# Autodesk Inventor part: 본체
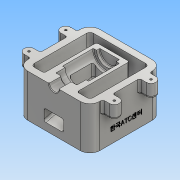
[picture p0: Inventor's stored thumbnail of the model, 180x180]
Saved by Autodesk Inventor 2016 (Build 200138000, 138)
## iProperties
Created: 2018-01
Part Number: 본체
Material: 알루미늄 6061
Document SubType Name: Modeling
Designer: Administrator
Density: 2.7 g/cm^3
Appearance: 알루미늄 - 평지
Mass: 993.349 g
Surface Area: 839.189 cm^2
Volume: 367.907 cm^3
Author: Administrator
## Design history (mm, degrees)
sketch "스케치1"
  geometry: L1 (-55, -55)-(55, -55); L2 (55, -55)-(55, 55); L3 (55, 55)-(-55, 55); L4 (-55, 55)-(-55, -55); L5 (-55, -55)-(55, 55); L6 (55, -55)-(-55, 55); 1 further point
  constraints: 12 end point, 2 midpoint, 2 parallel, 1 horizontal, 1 perpendicular
  dimensions: "d0" = 110 distance of L3.end L2.end; "d1" = 110 distance of L2.end L1.end
extrude "돌출1" new body sketch "스케치1" distance "d2" = 65; taper "d3" = 0 deg
sketch "스케치2"
  geometry: L1 (-55, -55)-(55, -55) reference; L2 (55, -55)-(55, 55) reference; L3 (55, 55)-(-55, 55) reference; L4 (-55, 55)-(-55, -55) reference; L5 (-45, 45)-(45, 45); L6 (45, 45)-(45, -45); L7 (45, -45)-(-45, -45); L8 (-45, -45)-(-45, 45); 1 further point
  constraints: 8 end point, 3 other
  dimensions: "d4" = 10 distance between parallel lines of L3 L5
extrude "돌출2" cut sketch "스케치2" stored distance "d5" = 65; taper "d6" = 0 deg
sketch "스케치3"
  geometry: L1 (55, -55)-(55, 55) reference; L2 (55, 55)-(-55, 55) reference; L3 (0, 0)-(0, 91.556); L4 (0, 0)-(113.572, 0); L5 (55, 35.5)-(65, 35.5); L6 (65, 35.5)-(65, 20.5); L7 (65, 20.5)-(55, 20.5); L8 (55, 20.5)-(55, 35.5); L9 (55, -20.5)-(55, -35.5); L10 (65, -35.5)-(65, -20.5); L11 (65, -20.5)-(55, -20.5); L12 (55, -35.5)-(65, -35.5); L13 (-65, -20.5)-(-55, -20.5); L14 (-55, 35.5)-(-65, 35.5); L15 (-65, 20.5)-(-55, 20.5); L16 (-55, 20.5)-(-55, 35.5); L17 (-65, 35.5)-(-65, 20.5); L18 (-55, -35.5)-(-65, -35.5); L19 (-65, -35.5)-(-65, -20.5); L20 (-55, -20.5)-(-55, -35.5); A1 r 7.5 centre (65, 28) between (65, 20.5) and (65, 35.5); A2 r 7.5 centre (65, -28) between (65, -35.5) and (65, -20.5); A3 r 7.5 centre (-65, 28) between (-65, 35.5) and (-65, 20.5); A4 r 7.5 centre (-65, -28) between (-65, -20.5) and (-65, -35.5)
  constraints: 36 end point, 15 symmetric about line, 8 point on circle, 4 centre point, 2 horizontal, 2 parallel, 1 midpoint, 1 perpendicular, 1 point on line, 1 vertical, 3 other
  dimensions: "d7" = 10 distance between parallel lines of L6 L1; "d8" = 27 distance from line of L2 A1.centre; "d9" = 7.5 radius of A1
extrude "돌출3" join sketch "스케치3" distance "d10" = 20; taper "d11" = 0 deg
sketch "스케치4"
  geometry: L1 (-45, 65)-(-45, 0) reference; L2 (-45, 8.564)-(35, 30); L3 (35, 30)-(35, 65); L4 (45, 0)-(-45, 0) reference; L5 (55, 0)-(55, 65) reference; L6 (-45, 65)-(45, 65) reference; 1 further point
  constraints: 4 end point, 2 point on line, 1 parallel
  dimensions: "d12" = 105 deg angle of L2 L1; "d13" = 30 distance from line of L4 L2.end; "d14" = 20 distance between parallel lines of L5 L3
extrude "돌출4" join sketch "스케치4" stored distance "d15" = 50; taper "d16" = 0 deg
sketch "스케치5"
  geometry: L1 (-55, -55)-(55, -55) reference; L2 (55, 55)-(-55, 55) reference; L3 (0, 0)-(0, 68.089); L4 (0, -45)-(0, 30); L5 (-15, 30)-(-15, 25); L6 (-15, 25)-(-20, 25); L7 (-20, 25)-(-20, -22); L8 (-20, -22)-(-16, -22); L9 (-16, -22)-(-16, -36); L10 (-16, -36)-(-7.5, -36); L11 (-7.5, -36)-(-7.5, -45); L12 (-45, -45)-(45, -45) reference; L13 (-15, 30)-(0, 30); L14 (-7.5, -45)-(-7.5, -55); L15 (0, -55)-(0, -45); L16 (0, -55)-(-7.5, -55)
  constraints: 26 end point, 8 perpendicular, 3 point on line, 2 midpoint, 1 collinear, 1 parallel, 1 vertical
  dimensions: "d17" = 15 diameter of L11 L3; "d18" = 32 diameter of L9 L3; "d19" = 40 diameter of L7 L3; "d20" = 30 diameter of L5 L3; "d21" = 19 distance between parallel lines of L1 L10; "d22" = 14 distance between parallel lines of L8 L10; "d23" = 47 distance between parallel lines of L6 L8; "d24" = 5 distance between parallel lines of L6 L13
revolve "회전1" sketch "스케치5" stored, may be unused: angle "d25" = 90 deg
sketch "스케치7"
  geometry: L1 (35, 30)-(-45, 8.564) reference; L2 (20, 31.157)-(-55, 11.061); L3 (-17, 39.243)-(-55, 29.061); L4 (-55, 0)-(-55, 65) reference; L5 (20, 31.157)-(20, 45); L6 (25, 45)-(-22, 45) reference; L7 (-17, 39.243)-(-17, 45); L8 (-22, 65)-(-22, 49) reference; L9 (-17, 45)-(20, 45); 1 further point
  constraints: 10 end point, 4 point on line, 3 parallel, 1 collinear, 1 vertical
  dimensions: "d29" = 5 distance between parallel lines of L1 L2; "d31" = 18 distance of L3.end L2.end; "d32" = 37 distance between parallel lines of L5 L7; "d33" = 5 distance between parallel lines of L8 L7
extrude "돌출5" cut sketch "스케치7" stored distance "d34" = 30; taper "d35" = 0 deg
sketch "스케치6"
  geometry: L1 (-20, 25)-(-15, 25) reference; L2 (-15, 20)-(15, 20); L3 (15, 20)-(15, -17); L4 (15, -17)-(-15, -17); L5 (-15, -17)-(-15, 20); 2 further points
  constraints: 8 end point, 2 parallel, 1 horizontal, 1 midpoint, 1 perpendicular, 1 vertical alignment
  dimensions: "d26" = 30 distance between parallel lines of L3 L5; "d27" = 37 distance between parallel lines of L4 L2; "d28" = 5 distance between parallel lines of L2 L1
extrude "돌출6" cut sketch "스케치6" stored distance "d36" = 30; taper "d37" = 0 deg
sketch "스케치8"
  geometry: L1 (0, 0)-(-65, 0) reference; L2 (0, 0)-(0, 110) reference; 2 further points
  constraints: 1 other
  dimensions: "d38" = 55 distance from line of L1 point (-20, 55); "d39" = 20 distance from line of L2 point (-20, 55)
feature "엠보싱1" sketch "스케치8" dims "d40" = 0.5, "d41" = 0
hole "구멍1" diameter "d44" = 3.242; stored, may be unused: countersink angle "d48" = 90 deg, drill point angle "d50" = 118 deg; dims "d42" = 10, "d43" = 10, "d45" = 9, "d46" = 4, "d47" = 2, "d49" = 11
fillet "모깎기1" dims "d57" = 15, "d58" = 5, "d59" = 3
chamfer "모따기1" distance "d60" = 1; stored, may be unused: second distance "d61" = 2, angle "d62" = 45 deg
fillet "모깎기2" dims "d63" = 1, "d64" = 3
fillet "모깎기3" dims "d65" = 3
node "솔리드1"
pattern_linear "직사각형 패턴1" dims "d53" = 56
